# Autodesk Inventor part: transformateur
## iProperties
Created: 2011-01
Part Number: transformateur
Document SubType Name: Modeling
Designer: eric
Density: 1 g/cm^3
Mass: 512.045 g
Surface Area: 448.509 cm^2
Volume: 512.045 cm^3
Author: eric
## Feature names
1. Base1
